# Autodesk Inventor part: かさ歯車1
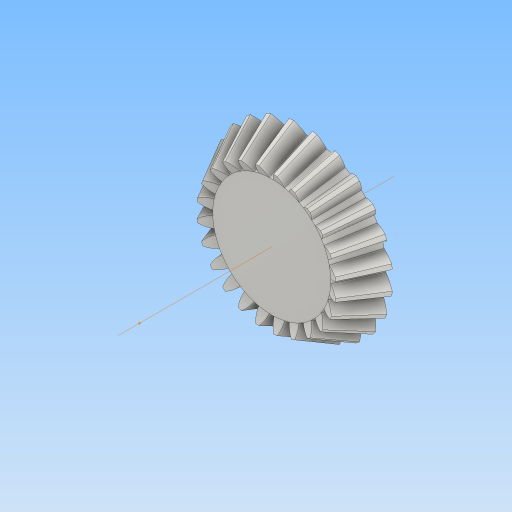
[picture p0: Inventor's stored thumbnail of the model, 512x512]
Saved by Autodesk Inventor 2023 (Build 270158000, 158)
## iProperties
Created: 2024-01
Part Number: かさ歯車1
Material: Steel, Mild
Document SubType Name: Modeling
Designer: kumagai
Categories: <?xml version="1.0" encoding="UTF-16"?> <MemberInstance><Categories><FamilyTemplate><FamilyTemplateParameter ValueType="xs:double" Id="1" ObjectReferenceKey="da
Mass: 60.9118 g
Surface Area: 34.3074 cm^2
Volume: 7.7496 cm^3
Density: 7.86 g/cm^3
Appearance: Steel
CustomPartVersion: 1
Author: kumagai
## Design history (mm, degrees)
node "上側の点"
node "メッシュ平面2"
sketch "歯のボディ スケッチ"
  geometry: L1 (0, 0)-(10.927, -24.537); L2 (10.927, -24.537)-(12.894, -23.553); L3 (12.894, -23.553)-(0, 0); L4 (12, -24)-(0, 0); L5 (8.483, -19.05)-(10.011, -18.286); L6 (10.927, -24.537)-(8.483, -19.05); L7 (12.894, -23.553)-(10.011, -18.286); L8 (0, -39.387)-(0, 6.564) reference; L9 (0, -24)-(12.894, -24)
  constraints: 16 end point, 4 point on line, 3 perpendicular, 2 collinear, 1 horizontal alignment, 1 vertical alignment
  dimensions: "d0" = 24 diameter of L4.start L8 (= da_de); "d1" = 21.85337 diameter of L1.end L8 (= da_dfe); "d2" = 25.78885 diameter of L2.end L8 (= da_dae); "d3" = 6 distance between parallel lines of L2 L5 (= da_b); "d4" = 23.55279 vertical distance of L2.end L1.start (= da_ve)
revolve "歯のボディ" sketch "歯のボディ スケッチ" stored, may be unused: angle "d5" = 90 deg
node "始点"
node "歯の平面"
sketch "開始スケッチ"
  geometry: L1 (0, -23.505)-(0, 10.645) reference; L2 (-0.407, -1.464)-(0.407, -1.464); A1 r 4.929 centre (-5.305, -2.008) between (-0.407, -1.464) and (-1.886, 1.542); A2 r 4.929 centre (5.305, -2.008) between (1.886, 1.542) and (0.407, -1.464); A3 r 15.076 centre (0, -13.416) between (1.886, 1.542) and (-1.886, 1.542); 1 further point
  constraints: 6 point on circle, 3 centre point, 3 symmetric about line, 2 end point, 1 coincident, 1 perpendicular, 1 other
  dimensions: "d7" = 4.92852 radius of A1 (= fd_rr); "d8" = 5.30503 horizontal distance of point (0, -13.416) A1.centre (= fd_x); "d9" = 11.4085 vertical distance of point (0, -13.416) A1.centre (= fd_y); "d57" = 15.07641 radius of A3 (= 0.5 x fd_dva + 0.3 x da_he); "d58" = 11.95241 distance from line of A3.centre L2 (= 0.5 x fd_dva - 1.12 x da_he)
node "終了側の点"
  node "終了平面"
sketch "終了側スケッチ"
  geometry: L1 (0, -15.354)-(0, 6.953) reference; L2 (-0.314, -1.131)-(0.314, -1.131); A1 r 3.806 centre (-4.097, -1.551) between (-0.314, -1.131) and (-1.456, 1.191); A2 r 3.806 centre (4.097, -1.551) between (1.456, 1.191) and (0.314, -1.131); A3 r 11.643 centre (0, -10.361) between (1.456, 1.191) and (-1.456, 1.191); 1 further point
  constraints: 6 point on circle, 3 centre point, 3 symmetric about line, 2 end point, 1 coincident, 1 other
  dimensions: "d12" = 3.80627 radius of A1 (computed from fd_rr, fd_ratio); "d15" = 4.09704 horizontal distance of A1.centre point (0, -10.361) (computed from fd_x, fd_ratio); "d16" = 8.81071 vertical distance of A1.centre point (0, -10.361) (computed from fd_y, fd_ratio); "d59" = 11.64342 radius of A3 (computed from d57, fd_ratio); "d60" = 9.23077 distance from line of A3.centre L2 (computed from d58, fd_ratio)
feature "Loft" sketch "終了側スケッチ" dims "d17" = 0, "d18" = 90 deg, "d19" = 0, "d20" = 90 deg, "d89" = 0, "da_teethtype" = 0 [user parameter]
sketch "3D スケッチ(右)"
  node "Helical Curve Right" dims "d65" = 164.5695 (computed from da_dm, da_delta, da_beta), "d66" = 31.5, "d67" = 24 (= da_de), "d68" = -4.63648 (= -da_delta), "d69" = 5.46495 (computed from fd_loft, da_delta)
node "終了平面(右)"
sketch "終了側スケッチ(右)"
  geometry: L1 (0, -18.698)-(0, 10.297) reference; L2 (-0.314, -1.131)-(0.314, -1.131); A1 r 3.806 centre (-4.097, -1.551) between (-0.314, -1.131) and (-1.456, 1.191); A2 r 3.806 centre (4.097, -1.551) between (1.456, 1.191) and (0.314, -1.131); A3 r 11.643 centre (0, -10.361) between (1.456, 1.191) and (-1.456, 1.191); 1 further point
  constraints: 6 point on circle, 3 centre point, 3 symmetric about line, 2 end point, 1 coincident, 1 perpendicular, 1 other
  dimensions: "d70" = 4.09704 horizontal distance of A3.centre A1.centre (computed from fd_x, fd_ratio); "d71" = 8.81071 vertical distance of point (0, -10.361) A1.centre (computed from fd_y, fd_ratio); "d72" = 3.80627 radius of A1 (computed from fd_rr, fd_ratio); "d73" = 9.23077 distance from line of point (0, -10.361) L2 (computed from d58, fd_ratio); "d74" = 11.64342 radius of A3 (computed from d57, fd_ratio)
feature "ロフト(右)" sketch "終了側スケッチ(右)" dims "d75" = 0, "d77" = 0, "d79" = 0, "d80" = 90 deg, "d85" = 20, "d92" = 90 deg, "d93" = 90 deg, "da_teethtype" = 0 [user parameter]
sketch "3D スケッチ(左)"
  node "Helical Curve Left" dims "d26" = 164.5695 (computed from da_dm, da_delta, da_beta), "d27" = 5.46495 (computed from fd_loft, da_delta), "d28" = 24 (= da_de), "d29" = -4.63648 (= -da_delta)
node "終了平面(左)"
sketch "終了側スケッチ(左)" dims "d56" = 8.95418 (derived)
  geometry: L1 (0, -32.408)-(0, 15.385) reference; L2 (-0.314, -1.131)-(0.314, -1.131); A1 r 3.806 centre (-4.097, -1.551) between (-0.314, -1.131) and (-1.456, 1.19); A2 r 3.806 centre (4.097, -1.551) between (1.456, 1.19) and (0.314, -1.131); A3 r 11.643 centre (0, -10.362) between (1.456, 1.19) and (-1.456, 1.19); 2 further points; 1 other entity
  constraints: 6 point on circle, 3 centre point, 3 symmetric about line, 2 end point, 1 coincident, 2 other
  dimensions: "d30" = 3.80627 radius of A1 (computed from fd_rr, fd_ratio); "d31" = 4.09704 horizontal distance of point (0, -10.362) A1.centre (computed from fd_x, fd_ratio); "d32" = 8.81071 vertical distance of A1.centre point (0, -10.362) (computed from fd_y, fd_ratio); "d61" = 11.64342 radius of A3 (computed from d57, fd_ratio); "d62" = 9.23077 distance from line of point (0, -10.362) L2 (computed from d58, fd_ratio)
feature "ロフト(左)" sketch "終了側スケッチ(左)" dims "d35" = 0, "d37" = 0, "d39" = 0, "d40" = 90 deg, "d84" = 10, "d90" = 90 deg, "d91" = 90 deg, "da_teethtype" = 0 [user parameter]
sketch "ボディ スケッチ"
  geometry: L1 (0, -35.038)-(0, -19.531) reference; L2 (10.927, -24.537)-(8.483, -19.05) reference; L3 (8.483, -19.05)-(0, -19.05); L4 (10.927, -24.537)-(0, -24.537)
  constraints: 4 end point, 2 perpendicular, 2 point on line
revolve "固定ボディ" sketch "ボディ スケッチ" stored, may be unused: angle "d46" = 90 deg
sketch "Sketch6"
  geometry: L1 (12, -24)-(0, 0) reference; L2 (0, -37.8)-(0, 6.3) reference
feature "ピッチ円直径" sketch "Sketch6" dims angle "d47" = 90 deg
body "Solid1"
pattern_circular "Circular Pattern" dims angle "d22" = 360 deg, "d88" = 0, "da_teethtype" = 0 [user parameter]
pattern_circular "放射状パターン(右)" dims angle "d82" = 360 deg, "da_teethtype" = 0 [user parameter]
pattern_circular "放射状パターン(左)" dims angle "d42" = 360 deg, "da_teethtype" = 0 [user parameter]
body "Srf1"
other parameters: "da_b" = 6 [user parameter; used in 2 equation terms], "da_de" = 24 [user parameter; used in 4 equation terms], "da_dae" = 25.78885 [user parameter; used in 2 equation terms], "da_dfe" = 21.85337 [user parameter; used in 1 equation term], "da_le" = 26.83282 [user parameter; used in 1 equation term], "da_omega" = 90 deg [user parameter; used in 1 equation term], "da_beta" = 0 [user parameter; used in 2 equation terms], "da_delta" = 4.63648 [user parameter; used in 8 equation terms], "da_alpha" = 20 deg [user parameter; used in 2 equation terms], "da_he" = 2.2 [user parameter; used in 4 equation terms], "da_ve" = 23.55279 [user parameter; used in 1 equation term], "fd_dv" = 26.83282 (computed from da_de, da_delta) [user parameter; used in 1 equation term], "fd_dva" = 28.83282 (computed from da_dae, da_delta) [user parameter; used in 3 equation terms], "fd_dvb" = 25.2146 (computed from fd_dv, da_alpha) [user parameter; used in 2 equation terms], "da_zv" = 268.32816 [user parameter; used in 1 equation term], "fd_loft" = 6.11 (= da_b + 0.05 x da_he) [user parameter; used in 4 equation terms], "fd_ratio" = 7.72294 (computed from da_le, fd_loft) [user parameter; used in 15 equation terms], "fd_rr" = 4.92852 (computed from fd_dd, fd_dvb) [user parameter; used in 6 equation terms], "fd_angle" = 0.59191 (computed from da_zv) [user parameter; used in 4 equation terms], "fd_x1" = 0.79366 (computed from da_dvw, fd_angle) [user parameter; used in 1 equation term], "fd_y1" = 13.39291 (computed from da_dvw, fd_angle) [user parameter; used in 1 equation term], "fd_x2" = 4.51137 (computed from fd_rr, fd_angle2, fd_angle) [user parameter; used in 1 equation term], "fd_y2" = 1.98441 (computed from fd_rr, fd_angle2, fd_angle) [user parameter; used in 1 equation term], "fd_x" = 5.30503 (= fd_x1 + fd_x2) [user parameter; used in 4 equation terms], "fd_y" = 11.4085 (= fd_y1 - fd_y2) [user parameter; used in 4 equation terms], "fd_angle2" = 3.55206 (computed from fd_dvb, fd_dd, da_alpha) [user parameter; used in 2 equation terms], "fd_dd" = 27.07282 (= fd_dva - 0.8 x da_he) [user parameter; used in 2 equation terms], "da_dvw" = 26.83282 [user parameter; used in 2 equation terms], "d11" = 6.11 (= fd_loft), "da_dm" = 21.31672 [user parameter; used in 2 equation terms], "da_x" = 0 [user parameter], "da_m" = 1 [user parameter], "d48" = 0, "d49" = 0, "d50" = 90 deg (= da_omega), "d51" = 7.5 deg (computed from da_z), "d52" = 0, "d53" = 0, "d54" = 0
